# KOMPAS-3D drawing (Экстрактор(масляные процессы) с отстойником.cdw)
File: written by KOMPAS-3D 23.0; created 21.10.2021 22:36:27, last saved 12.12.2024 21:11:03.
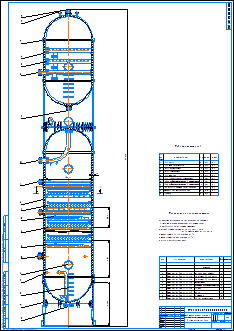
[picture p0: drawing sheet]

Sheet 1: A1, portrait

Document properties: Автор: DDiniev@yandex.ru; Полное имя файла: G:\Учёба\Чертежи\Экстрактор 3 сложн\Для публикации\EKSTARKTsIONNAYa_KOLONNA__kopia.cdw

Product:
- Part/product: (unnamed)  | designation УТЭК.18.02.09.ПП.00.00.000.ВО

Title block, sheet 1: Наименование: Экстракционная колонна / селективнной отчистки масел / Чертеж общего вида; designation: УТЭК.18.02.09.ПП.00.00.000.ВО; scale: 1:25; Количество листов документа: 1; Форматы листов документа: A1; stored path: C:\Users\DDini\Desktop\Чертеж курсовой.cdw

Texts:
  Normal
  СК 1
  Обо
  зна
  чение
  Кол
  Ду мм
  Ру МПа
  Ввод фенольной воды
  Ввод сырья
  Вывод экстракта
  Вывод рафината
  Ввод фенола
  Ввод охлажденного рафината
  Вывод рафинатной смеси в отстойник
  Ввод рафинатной смеси в отстойник
  Для предохранительного клапана
  Штуцер для термокармана
  Люк-лаз
  Таблица штуцеров
  Техническая характеристика
  1 Аппарат предназначен для удаления смолистых
  веществ и полициклических ароматических
  углеводородов из деасфальтизата
  2 Производительность по сырью 14000 кг/ч
  3 Температура верха колонны 80 С
  4 Температура низа колонны 60 С
  5 Среда: слабокоррозионная
  Поз.
  Кол.
  Детали
  УТЭК.18.02.09.ПП.00.00.001
  Тарелка жалюзийная
  УТЭК.18.02.09.ПП.00.00.002
  Коллектор ввода сырья
  УТЭК.18.02.09.ПП.00.00.004
  Коллектор ввода фенола
  УТЭК.18.02.09.ПП.00.00.005
  Отстойник
  УТЭК.18.02.09.ПП.00.00.006
  Коллектор ввода фенольной воды
  УТЭК.18.02.09.ПП.00.00.008
  УТЭК.18.02.09.ПП.00.00.009
  УТЭК.18.02.09.ПП.00.00.010
  Корпус
  Опора
  Лестница
  Кольцо жесткости
  Стили документа
Dimensions and other numbers on the sheet: 3; 4; 100; 4,0; 1; 150; 2; 25; 500; 22465; 65; 3800; 1150; 2150; 2753; 5; 6; 7; 8; 9; 1:25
